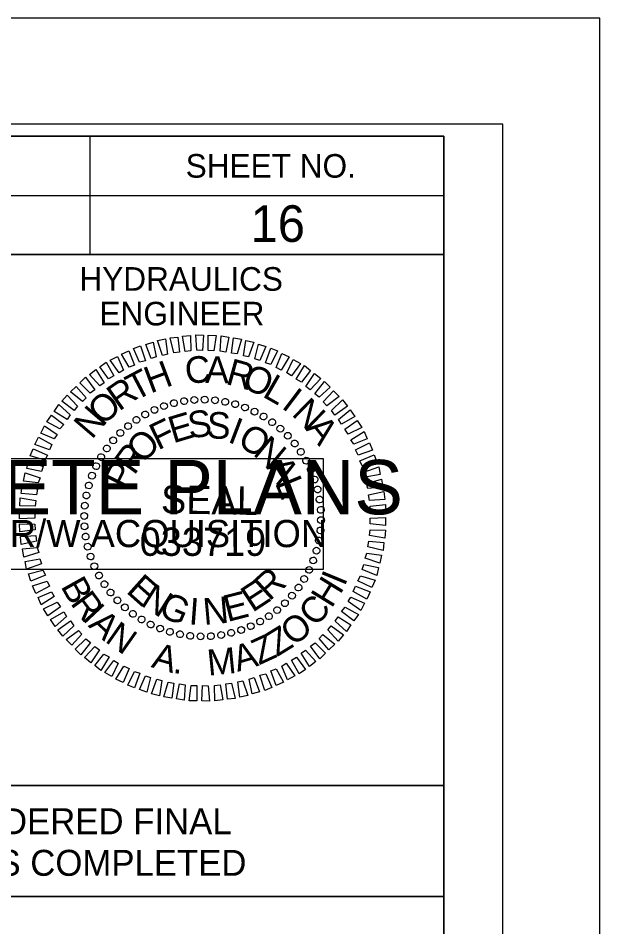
# Model space of a CAD drawing. Extents: x 1779926 to 1781626, y 618464 to 619564.
# Drawn here: x 1781502.8 to 1781626, y 619371.7 to 619564.2 of the extents above; entities that cross this region are included whole.
import ezdxf

# ---------------------------------------------------------------- set-up
doc = ezdxf.new("R2010")
doc.units = 0
for name, color, linetype in [('Old_Level_58', 7, 'Continuous'), ('Sheet Data Field CELL', 7, 'Continuous'), ('Sheet Plot Border Inside CELL', 7, 'Continuous'), ('Sheet Plot Border Outside CELL', 7, 'Continuous'), ('Sheet Professional Seal CELL', 7, 'Continuous'), ('Sheet Profile CELL', 7, 'Continuous'), ('Sheet Profile Grid Major CELL', 7, 'Continuous'), ('Sheet Profile Grid Minor CELL', 7, 'Continuous'), ('Sheet Sticker Exception Certification CELL', 7, 'Continuous'), ('Sheet Sticker Incomplete CELL', 7, 'Continuous')]:
    doc.layers.add(name, color=color, linetype=linetype)

msp = doc.modelspace()

# ---------------------------------------------------------------- linework, layer by layer
at = {"layer": 'Old_Level_58'}
msp.add_lwpolyline([(1781392.9, 619378.14), (1781592.95, 619378.14), (1781592.95, 619314.19), (1781392.9, 619314.19)], close=True, dxfattribs=at)
at = {"layer": 'Sheet Plot Border Inside CELL'}
msp.add_lwpolyline([(1779938.96, 618486.64), (1781605.46, 618486.64), (1781605.46, 619541.74), (1779938.96, 619541.74)], close=True, dxfattribs=at)
at = {"layer": 'Sheet Plot Border Outside CELL'}
msp.add_lwpolyline([(1779925.96, 618464.19), (1781625.96, 618464.19), (1781625.96, 619564.19), (1779925.96, 619564.19)], close=True, dxfattribs=at)
at = {"layer": 'Sheet Professional Seal CELL'}
for p, q in [((1781535.76, 619482.64), (1781535.76, 619482.64)), ((1781537.96, 619483.04), (1781537.96, 619483.04)), ((1781540.11, 619483.34), (1781540.11, 619483.34)), ((1781542.31, 619483.39), (1781542.31, 619483.39)), ((1781544.51, 619483.24), (1781544.51, 619483.24)), ((1781546.66, 619482.89), (1781546.66, 619482.89)), ((1781548.76, 619482.44), (1781548.76, 619482.44)), ((1781531.66, 619481.24), (1781531.66, 619481.24)), ((1781533.66, 619482.04), (1781533.66, 619482.04)), ((1781550.86, 619481.74), (1781550.86, 619481.74)), ((1781552.86, 619480.84), (1781552.86, 619480.84)), ((1781527.81, 619479.09), (1781527.81, 619479.09)), ((1781529.71, 619480.24), (1781529.71, 619480.24)), ((1781554.81, 619479.84), (1781554.81, 619479.84)), ((1781556.61, 619478.59), (1781556.61, 619478.59)), ((1781526.06, 619477.84), (1781526.06, 619477.84)), ((1781558.36, 619477.24), (1781558.36, 619477.24)), ((1781522.91, 619474.79), (1781522.91, 619474.79)), ((1781524.41, 619476.34), (1781524.41, 619476.34)), ((1781559.91, 619475.74), (1781559.91, 619475.74)), ((1781521.56, 619473.04), (1781521.56, 619473.04)), ((1781561.41, 619474.09), (1781561.41, 619474.09)), ((1781520.31, 619471.24), (1781520.31, 619471.24)), ((1781562.66, 619472.34), (1781562.66, 619472.34)), ((1781519.31, 619469.29), (1781519.31, 619469.29)), ((1781563.81, 619470.44), (1781563.81, 619470.44)), ((1781518.41, 619467.29), (1781518.41, 619467.29)), ((1781564.81, 619468.49), (1781564.81, 619468.49)), ((1781517.71, 619465.19), (1781517.71, 619465.19)), ((1781565.61, 619466.49), (1781565.61, 619466.49)), ((1781517.26, 619463.09), (1781517.26, 619463.09)), ((1781566.21, 619464.39), (1781566.21, 619464.39)), ((1781566.61, 619462.19), (1781566.61, 619462.19)), ((1781516.91, 619460.94), (1781516.91, 619460.94)), ((1781566.91, 619460.04), (1781566.91, 619460.04)), ((1781516.76, 619458.74), (1781516.76, 619458.74)), ((1781541.86, 619458.29), (1781541.86, 619458.29)), ((1781566.96, 619457.84), (1781566.96, 619457.84)), ((1781516.81, 619456.54), (1781516.81, 619456.54)), ((1781566.81, 619455.64), (1781566.81, 619455.64)), ((1781517.11, 619454.39), (1781517.11, 619454.39)), ((1781566.46, 619453.49), (1781566.46, 619453.49)), ((1781517.51, 619452.19), (1781517.51, 619452.19)), ((1781518.11, 619450.09), (1781518.11, 619450.09)), ((1781566.01, 619451.39), (1781566.01, 619451.39)), ((1781518.91, 619448.09), (1781518.91, 619448.09)), ((1781565.31, 619449.29), (1781565.31, 619449.29)), ((1781519.91, 619446.14), (1781519.91, 619446.14)), ((1781564.41, 619447.29), (1781564.41, 619447.29)), ((1781521.06, 619444.24), (1781521.06, 619444.24)), ((1781563.41, 619445.34), (1781563.41, 619445.34)), ((1781522.31, 619442.49), (1781522.31, 619442.49)), ((1781562.16, 619443.54), (1781562.16, 619443.54)), ((1781523.81, 619440.84), (1781523.81, 619440.84)), ((1781559.31, 619440.24), (1781559.31, 619440.24)), ((1781560.81, 619441.79), (1781560.81, 619441.79)), ((1781525.36, 619439.34), (1781525.36, 619439.34)), ((1781557.66, 619438.74), (1781557.66, 619438.74)), ((1781527.11, 619437.99), (1781527.11, 619437.99)), ((1781528.91, 619436.74), (1781528.91, 619436.74)), ((1781554.01, 619436.34), (1781554.01, 619436.34)), ((1781555.91, 619437.49), (1781555.91, 619437.49)), ((1781530.86, 619435.74), (1781530.86, 619435.74)), ((1781532.86, 619434.84), (1781532.86, 619434.84)), ((1781550.06, 619434.54), (1781550.06, 619434.54)), ((1781552.06, 619435.34), (1781552.06, 619435.34)), ((1781534.96, 619434.14), (1781534.96, 619434.14)), ((1781537.06, 619433.69), (1781537.06, 619433.69)), ((1781539.21, 619433.34), (1781539.21, 619433.34)), ((1781541.41, 619433.19), (1781541.41, 619433.19)), ((1781543.61, 619433.24), (1781543.61, 619433.24)), ((1781545.76, 619433.54), (1781545.76, 619433.54)), ((1781547.96, 619433.94), (1781547.96, 619433.94))]:
    msp.add_line(p, q, dxfattribs=at)
for points in [[(1781533.36, 619492.74), (1781532.31, 619495.89), (1781534.01, 619496.24), (1781534.41, 619492.99)], [(1781535.76, 619493.29), (1781534.96, 619496.49), (1781536.61, 619496.64), (1781536.96, 619493.44)], [(1781538.16, 619493.59), (1781537.61, 619496.79), (1781539.31, 619496.99), (1781539.36, 619493.74)], [(1781540.66, 619493.84), (1781540.41, 619497.09), (1781542.06, 619497.04), (1781541.86, 619493.79)], [(1781543.06, 619493.79), (1781543.06, 619497.04), (1781544.71, 619496.99), (1781544.26, 619493.74)], [(1781545.56, 619493.64), (1781545.76, 619496.89), (1781547.41, 619496.59), (1781546.76, 619493.44)], [(1781547.96, 619493.24), (1781548.41, 619496.44), (1781550.06, 619496.19), (1781549.16, 619493.09)], [(1781550.51, 619492.69), (1781551.01, 619495.94), (1781552.71, 619495.54), (1781551.56, 619492.44)], [(1781528.51, 619491.29), (1781527.21, 619494.19), (1781528.71, 619494.79), (1781529.76, 619491.59)], [(1781530.96, 619492.09), (1781529.81, 619495.09), (1781531.36, 619495.54), (1781532.01, 619492.44)], [(1781552.91, 619492.04), (1781553.66, 619495.14), (1781555.21, 619494.64), (1781553.96, 619491.69)], [(1781555.16, 619491.14), (1781556.31, 619494.29), (1781557.71, 619493.69), (1781556.31, 619490.79)], [(1781524.16, 619489.04), (1781522.31, 619491.74), (1781523.86, 619492.54), (1781525.11, 619489.64)], [(1781526.31, 619490.24), (1781524.71, 619493.04), (1781526.26, 619493.74), (1781527.41, 619490.69)], [(1781557.41, 619490.19), (1781558.66, 619493.14), (1781560.21, 619492.44), (1781558.51, 619489.64)], [(1781521.96, 619487.79), (1781520.11, 619490.34), (1781521.41, 619491.29), (1781523.06, 619488.39)], [(1781559.71, 619489.04), (1781561.06, 619491.89), (1781562.56, 619491.04), (1781560.66, 619488.44)], [(1781561.66, 619487.69), (1781563.41, 619490.59), (1781564.71, 619489.54), (1781562.76, 619487.09)], [(1781518.06, 619484.74), (1781515.86, 619486.94), (1781517.06, 619488.14), (1781519.01, 619485.44)], [(1781520.06, 619486.29), (1781517.91, 619488.69), (1781519.26, 619489.74), (1781521.01, 619486.94)], [(1781563.71, 619486.19), (1781565.56, 619488.94), (1781566.86, 619487.84), (1781564.66, 619485.49)], [(1781516.41, 619482.99), (1781513.86, 619485.04), (1781515.11, 619486.19), (1781517.21, 619483.79)], [(1781565.61, 619484.64), (1781567.66, 619487.24), (1781568.86, 619486.04), (1781566.56, 619483.89)], [(1781514.66, 619481.09), (1781512.06, 619483.04), (1781513.16, 619484.34), (1781515.36, 619481.99)], [(1781567.41, 619482.89), (1781569.56, 619485.24), (1781570.76, 619484.04), (1781568.16, 619482.09)], [(1781513.16, 619479.19), (1781510.46, 619480.89), (1781511.41, 619482.34), (1781513.81, 619480.14)], [(1781569.16, 619481.09), (1781571.46, 619483.34), (1781572.51, 619481.99), (1781569.86, 619480.09)], [(1781570.66, 619479.14), (1781573.11, 619481.24), (1781574.06, 619479.79), (1781571.26, 619478.19)], [(1781511.66, 619477.19), (1781508.86, 619478.69), (1781509.86, 619480.09), (1781512.46, 619478.09)], [(1781571.96, 619477.09), (1781574.61, 619478.99), (1781575.56, 619477.49), (1781572.66, 619476.09)], [(1781510.46, 619475.04), (1781507.61, 619476.29), (1781508.36, 619477.84), (1781511.06, 619475.99)], [(1781573.26, 619474.89), (1781576.06, 619476.64), (1781576.71, 619475.09), (1781573.86, 619473.94)], [(1781509.46, 619472.74), (1781506.36, 619473.89), (1781507.11, 619475.44), (1781509.96, 619473.84)], [(1781508.46, 619470.54), (1781505.36, 619471.44), (1781506.01, 619472.99), (1781509.01, 619471.59)], [(1781574.26, 619472.74), (1781577.21, 619474.24), (1781577.86, 619472.64), (1781574.76, 619471.64)], [(1781575.16, 619470.39), (1781578.21, 619471.69), (1781578.76, 619470.14), (1781575.66, 619469.34)], [(1781507.71, 619468.14), (1781504.61, 619468.79), (1781504.96, 619470.44), (1781508.11, 619469.19)], [(1781575.96, 619467.99), (1781579.16, 619469.14), (1781579.46, 619467.49), (1781576.31, 619466.94)], [(1781507.06, 619465.74), (1781503.96, 619466.14), (1781504.31, 619467.84), (1781507.46, 619466.79)], [(1781506.66, 619463.19), (1781503.46, 619463.49), (1781503.66, 619465.19), (1781506.91, 619464.39)], [(1781576.56, 619465.59), (1781579.71, 619466.54), (1781580.01, 619464.84), (1781576.86, 619464.54)], [(1781577.01, 619463.19), (1781580.26, 619463.89), (1781580.41, 619462.19), (1781577.21, 619461.99)], [(1781506.41, 619460.79), (1781503.16, 619460.89), (1781503.26, 619462.54), (1781506.51, 619461.99)], [(1781577.31, 619460.79), (1781580.56, 619461.19), (1781580.66, 619459.49), (1781577.41, 619459.59)], [(1781506.36, 619458.29), (1781503.11, 619458.14), (1781503.11, 619459.84), (1781506.36, 619459.49)], [(1781577.36, 619458.29), (1781580.61, 619458.44), (1781580.61, 619456.74), (1781577.36, 619457.09)], [(1781506.41, 619455.79), (1781503.16, 619455.39), (1781503.06, 619457.09), (1781506.31, 619456.99)], [(1781577.31, 619455.79), (1781580.56, 619455.69), (1781580.46, 619454.04), (1781577.21, 619454.59)], [(1781506.71, 619453.39), (1781503.46, 619452.69), (1781503.31, 619454.39), (1781506.51, 619454.59)], [(1781507.16, 619450.99), (1781504.01, 619450.04), (1781503.71, 619451.74), (1781506.86, 619452.04)], [(1781577.06, 619453.39), (1781580.26, 619453.09), (1781580.06, 619451.39), (1781576.81, 619452.19)], [(1781507.76, 619448.59), (1781504.56, 619447.44), (1781504.26, 619449.09), (1781507.41, 619449.64)], [(1781576.66, 619450.84), (1781579.76, 619450.44), (1781579.41, 619448.74), (1781576.26, 619449.79)], [(1781576.01, 619448.44), (1781579.11, 619447.79), (1781578.76, 619446.14), (1781575.61, 619447.39)], [(1781508.56, 619446.19), (1781505.51, 619444.89), (1781504.96, 619446.44), (1781508.06, 619447.24)], [(1781575.26, 619446.04), (1781578.36, 619445.14), (1781577.71, 619443.59), (1781574.71, 619444.99)], [(1781509.46, 619443.84), (1781506.51, 619442.34), (1781505.86, 619443.94), (1781508.96, 619444.94)], [(1781574.26, 619443.84), (1781577.36, 619442.69), (1781576.61, 619441.14), (1781573.76, 619442.74)], [(1781510.46, 619441.69), (1781507.66, 619439.94), (1781507.01, 619441.49), (1781509.86, 619442.64)], [(1781511.76, 619439.49), (1781509.11, 619437.59), (1781508.16, 619439.09), (1781511.06, 619440.49)], [(1781573.26, 619441.54), (1781576.11, 619440.29), (1781575.36, 619438.74), (1781572.66, 619440.59)], [(1781513.06, 619437.44), (1781510.61, 619435.34), (1781509.66, 619436.79), (1781512.46, 619438.39)], [(1781572.06, 619439.39), (1781574.86, 619437.89), (1781573.86, 619436.49), (1781571.26, 619438.49)], [(1781514.56, 619435.49), (1781512.26, 619433.24), (1781511.21, 619434.59), (1781513.86, 619436.49)], [(1781570.56, 619437.39), (1781573.26, 619435.69), (1781572.31, 619434.24), (1781569.91, 619436.44)], [(1781516.31, 619433.69), (1781514.16, 619431.34), (1781512.96, 619432.54), (1781515.56, 619434.49)], [(1781569.06, 619435.49), (1781571.66, 619433.54), (1781570.56, 619432.24), (1781568.36, 619434.59)], [(1781518.11, 619431.94), (1781516.06, 619429.34), (1781514.86, 619430.54), (1781517.16, 619432.69)], [(1781567.31, 619433.59), (1781569.86, 619431.54), (1781568.61, 619430.39), (1781566.51, 619432.79)], [(1781520.01, 619430.39), (1781518.16, 619427.64), (1781516.86, 619428.74), (1781519.06, 619431.09)], [(1781565.66, 619431.84), (1781567.86, 619429.64), (1781566.66, 619428.44), (1781564.71, 619431.14)], [(1781522.06, 619428.89), (1781520.31, 619425.99), (1781519.01, 619427.04), (1781520.96, 619429.49)], [(1781561.76, 619428.79), (1781563.61, 619426.24), (1781562.31, 619425.29), (1781560.66, 619428.19)], [(1781563.66, 619430.29), (1781565.81, 619427.89), (1781564.46, 619426.84), (1781562.71, 619429.64)], [(1781524.01, 619427.54), (1781522.66, 619424.69), (1781521.16, 619425.54), (1781523.06, 619428.14)], [(1781526.31, 619426.39), (1781525.06, 619423.44), (1781523.51, 619424.14), (1781525.21, 619426.94)], [(1781559.56, 619427.54), (1781561.41, 619424.84), (1781559.86, 619424.04), (1781558.61, 619426.94)], [(1781528.56, 619425.44), (1781527.41, 619422.29), (1781526.01, 619422.89), (1781527.41, 619425.79)], [(1781530.81, 619424.54), (1781530.06, 619421.44), (1781528.51, 619421.94), (1781529.76, 619424.89)], [(1781555.21, 619425.29), (1781556.51, 619422.39), (1781555.01, 619421.79), (1781553.96, 619424.99)], [(1781557.41, 619426.34), (1781559.01, 619423.54), (1781557.46, 619422.84), (1781556.31, 619425.89)], [(1781533.21, 619423.89), (1781532.71, 619420.64), (1781531.01, 619421.04), (1781532.16, 619424.14)], [(1781535.76, 619423.34), (1781535.31, 619420.14), (1781533.66, 619420.39), (1781534.56, 619423.49)], [(1781538.16, 619422.94), (1781537.96, 619419.69), (1781536.31, 619419.99), (1781536.96, 619423.14)], [(1781540.66, 619422.79), (1781540.66, 619419.54), (1781539.01, 619419.59), (1781539.46, 619422.84)], [(1781543.06, 619422.74), (1781543.31, 619419.49), (1781541.66, 619419.54), (1781541.86, 619422.79)], [(1781545.56, 619422.99), (1781546.11, 619419.79), (1781544.41, 619419.59), (1781544.36, 619422.84)], [(1781547.96, 619423.29), (1781548.76, 619420.09), (1781547.11, 619419.94), (1781546.76, 619423.14)], [(1781550.36, 619423.84), (1781551.41, 619420.69), (1781549.71, 619420.34), (1781549.31, 619423.59)], [(1781552.76, 619424.49), (1781553.91, 619421.49), (1781552.36, 619421.04), (1781551.71, 619424.14)]]:
    msp.add_lwpolyline(points, close=True, dxfattribs=at)
for centre, major_axis in [((1781533.69, 619482.01), (-0.234, 0.681)), ((1781535.79, 619482.63), (-0.174, 0.699)), ((1781537.93, 619483.06), (-0.113, 0.711)), ((1781540.11, 619483.31), (-0.05, 0.718)), ((1781542.29, 619483.37), (0.013, 0.72)), ((1781544.48, 619483.24), (0.075, 0.716)), ((1781546.64, 619482.91), (0.137, 0.707)), ((1781548.77, 619482.4), (0.198, 0.692)), ((1781550.84, 619481.71), (0.258, 0.672)), ((1781529.7, 619480.23), (-0.349, 0.63)), ((1781531.66, 619481.2), (-0.293, 0.658)), ((1781552.85, 619480.83), (0.316, 0.647)), ((1781554.77, 619479.79), (0.371, 0.617)), ((1781526.07, 619477.78), (-0.453, 0.56)), ((1781527.83, 619479.09), (-0.403, 0.597)), ((1781556.6, 619478.58), (0.423, 0.582)), ((1781524.43, 619476.33), (-0.5, 0.518)), ((1781558.31, 619477.22), (0.472, 0.543)), ((1781522.93, 619474.75), (-0.543, 0.472)), ((1781559.9, 619475.72), (0.518, 0.5)), ((1781561.35, 619474.08), (0.56, 0.453)), ((1781521.57, 619473.03), (-0.582, 0.423)), ((1781562.65, 619472.32), (0.597, 0.403)), ((1781520.36, 619471.21), (-0.617, 0.371)), ((1781563.79, 619470.45), (0.63, 0.349)), ((1781519.31, 619469.29), (-0.647, 0.316)), ((1781564.77, 619468.49), (0.658, 0.293)), ((1781518.44, 619467.28), (-0.672, 0.258)), ((1781565.57, 619466.46), (0.681, 0.234)), ((1781517.75, 619465.21), (-0.692, 0.198)), ((1781566.19, 619464.36), (0.699, 0.174)), ((1781517.24, 619463.08), (-0.707, 0.137)), ((1781516.91, 619460.91), (-0.716, 0.075)), ((1781566.63, 619462.22), (0.711, 0.113)), ((1781516.78, 619458.73), (-0.72, 0.013)), ((1781566.88, 619460.04), (0.718, 0.05)), ((1781566.93, 619457.86), (0.72, -0.013)), ((1781516.84, 619456.54), (-0.718, -0.05)), ((1781566.8, 619455.67), (0.716, -0.075)), ((1781517.09, 619454.37), (-0.711, -0.113)), ((1781566.48, 619453.51), (0.707, -0.137)), ((1781517.52, 619452.23), (-0.699, -0.174)), ((1781565.96, 619451.38), (0.692, -0.198)), ((1781518.14, 619450.13), (-0.681, -0.234)), ((1781565.27, 619449.31), (0.672, -0.258)), ((1781518.94, 619448.09), (-0.658, -0.293)), ((1781564.4, 619447.3), (0.647, -0.316)), ((1781519.92, 619446.13), (-0.63, -0.349)), ((1781563.35, 619445.38), (0.617, -0.371)), ((1781521.06, 619444.27), (-0.597, -0.403)), ((1781562.15, 619443.55), (0.582, -0.423)), ((1781522.37, 619442.51), (-0.56, -0.453)), ((1781560.78, 619441.84), (0.543, -0.472)), ((1781523.82, 619440.87), (-0.518, -0.5)), ((1781525.4, 619439.37), (-0.472, -0.543)), ((1781559.28, 619440.25), (0.5, -0.518)), ((1781527.11, 619438), (-0.423, -0.582)), ((1781555.88, 619437.5), (0.403, -0.597)), ((1781557.64, 619438.8), (0.453, -0.56)), ((1781528.94, 619436.8), (-0.371, -0.617)), ((1781530.86, 619435.75), (-0.316, -0.647)), ((1781552.06, 619435.38), (0.293, -0.658)), ((1781554.02, 619436.36), (0.349, -0.63)), ((1781532.87, 619434.88), (-0.258, -0.672)), ((1781534.94, 619434.18), (-0.198, -0.692)), ((1781537.07, 619433.67), (-0.137, -0.707)), ((1781545.78, 619433.52), (0.113, -0.711)), ((1781547.92, 619433.96), (0.174, -0.699)), ((1781550.02, 619434.58), (0.234, -0.681)), ((1781539.23, 619433.35), (-0.075, -0.716)), ((1781541.42, 619433.22), (-0.013, -0.72)), ((1781543.61, 619433.27), (0.05, -0.718))]:
    msp.add_ellipse(centre, major_axis=major_axis, ratio=0.999708, dxfattribs=at)
at = {"layer": 'Sheet Profile CELL'}
for p, q in [((1781517.96, 619539.14), (1781517.96, 619514.14)), ((1781392.91, 619526.64), (1781592.96, 619526.64))]:
    msp.add_line(p, q, dxfattribs=at)
for points in [[(1781592.96, 619539.19), (1780092.96, 619539.19), (1780092.96, 618489.19), (1781592.96, 618489.19)], [(1781392.91, 619539.19), (1781592.96, 619539.19), (1781592.96, 619514.14), (1781392.91, 619514.14)], [(1781492.96, 619514.14), (1781592.96, 619514.14), (1781592.96, 619401.64), (1781492.96, 619401.64)]]:
    msp.add_lwpolyline(points, close=True, dxfattribs=at)
at = {"layer": 'Sheet Profile Grid Major CELL'}
msp.add_lwpolyline([(1781542.96, 619314.19), (1781542.96, 619039.19), (1781592.96, 619039.19), (1781592.96, 619389.19)], dxfattribs=at)
at = {"layer": 'Sheet Sticker Exception Certification CELL'}
for p, q in [((1781392.91, 619401.64), (1781592.95, 619401.64)), ((1781392.91, 619401.64), (1781592.95, 619401.64)), ((1781592.95, 619401.63), (1781592.95, 619378.13)), ((1781592.95, 619401.63), (1781592.95, 619378.13)), ((1781592.95, 619378.14), (1781392.91, 619378.14)), ((1781592.95, 619378.14), (1781392.91, 619378.14))]:
    msp.add_line(p, q, dxfattribs=at)
at = {"layer": 'Sheet Sticker Incomplete CELL'}
msp.add_lwpolyline([(1781420.37, 619447.38), (1781420.37, 619470.88), (1781567.37, 619470.88), (1781567.37, 619447.38)], close=True, dxfattribs=at)

# ---------------------------------------------------------------- texts
at = {"layer": 'Sheet Data Field CELL'}
msp.add_text('16', height=7.75, dxfattribs=at).set_placement((1781552, 619516.8))
at = {"layer": 'Sheet Professional Seal CELL'}
for s, height, rotation, p in [('C', 5.64, 6.2199, (1781538.41, 619486.64)), ('A', 5.64, 359.0203, (1781542.36, 619486.94)), ('R', 5.64, 344.6211, (1781546.56, 619486.74)), ('T', 5.64, 27.8198, (1781527.56, 619482.99)), ('H', 5.64, 20.6195, (1781530.81, 619484.64)), ('O', 5.64, 337.4212, (1781549.91, 619485.99)), ('L', 5.64, 330.2209, (1781554.31, 619484.14)), ('R', 5.64, 35.0205, (1781524.16, 619480.79)), ('O', 5.64, 42.2217, (1781520.71, 619477.69)), ('I', 5.64, 323.0201, (1781558.36, 619481.74)), ('N', 5.64, 315.8189, (1781560.51, 619480.19)), ('N', 5.64, 49.4235, (1781518.41, 619474.79)), ('E', 5.64, 16.6111, (1781535.61, 619474.09)), ('S', 5.64, 7.2556, (1781539.06, 619475.14)), ('S', 5.64, 357.9004, (1781542.66, 619475.19)), ('F', 5.64, 25.967, (1781532.41, 619472.59)), ('I', 5.64, 339.1896, (1781546.96, 619474.49)), ('A', 5.64, 308.6172, (1781563.46, 619477.24)), ('O', 5.64, 44.6812, (1781529.11, 619469.64)), ('O', 5.64, 329.8335, (1781548.96, 619473.79)), ('N', 5.64, 320.4766, (1781552.31, 619471.79)), ('R', 5.64, 54.0397, (1781527.36, 619467.19)), ('P', 5.64, 63.3989, (1781525.76, 619463.99)), ('A', 5.64, 301.7603, (1781555.16, 619469.19)), ('L', 5.64, 292.4008, (1781557.11, 619465.74)), ('SEAL', 5.998, 359, (1781533.01, 619459.29)), ('E', 5.64, 318.2769, (1781525.46, 619442.64)), ('R', 5.64, 42.4814, (1781555.96, 619440.54)), ('N', 5.64, 327.634, (1781528.46, 619439.94)), ('E', 5.64, 33.1241, (1781552.41, 619438.19)), ('G', 5.64, 336.9902, (1781532.26, 619437.69)), ('E', 5.64, 14.4118, (1781547.11, 619436.24)), ('I', 5.64, 355.7012, (1781538.81, 619435.79)), ('N', 5.64, 5.0564, (1781542.16, 619435.64))]:
    msp.add_text(s, height=height, rotation=rotation, dxfattribs=at).set_placement(p)
at = {"layer": 'Sheet Profile CELL'}
for s, p in [('SHEET NO.', (1781538.27, 619530.4)), ('HYDRAULICS', (1781515.77, 619506.45)), ('ENGINEER', (1781520.02, 619499.1))]:
    msp.add_text(s, height=5, dxfattribs=at).set_placement(p)
at = {"layer": 'Sheet Profile Grid Minor CELL'}
msp.add_text('033719', height=5.998, dxfattribs=at).set_placement((1781528.54, 619450.28))
for s, rotation, p in [('B', 299.1529, (1781511.71, 619443.85)), ('H', 58.3478, (1781569.17, 619439.02)), ('I', 67.5926, (1781571.91, 619443.66)), ('R', 306.2797, (1781513.73, 619440.22)), ('I', 313.2061, (1781516.12, 619436.96)), ('C', 49.4751, (1781565.87, 619435.04)), ('A', 316.7266, (1781517.48, 619435.42)), ('N', 324.9124, (1781520.98, 619432.19)), ('O', 38.7706, (1781561.13, 619430.98)), ('Z', 31.6438, (1781557.59, 619428.8)), ('Z', 24.517, (1781553.81, 619427.08)), ('A', 344.2893, (1781530.82, 619426.74)), ('M', 5.6554, (1781543.08, 619424.89)), ('A', 16.3312, (1781549.25, 619425.69)), ('.', 352.4751, (1781535.43, 619425.49))]:
    msp.add_text(s, height=5.5, rotation=rotation, dxfattribs=at).set_placement(p)
at = {"layer": 'Sheet Sticker Exception Certification CELL'}
for s, p in [('DOCUMENT NOT CONSIDERED FINAL', (1781413.98, 619391.3)), ('DOCUMENT NOT CONSIDERED FINAL', (1781413.98, 619391.3)), ('UNLESS ALL SIGNATURES COMPLETED', (1781408.91, 619382.5)), ('UNLESS ALL SIGNATURES COMPLETED', (1781408.91, 619382.5))]:
    msp.add_text(s, height=5.5, dxfattribs=at).set_placement(p)
at = {"layer": 'Sheet Sticker Incomplete CELL'}
for s, height, p in [('INCOMPLETE PLANS', 11.52, (1781429.32, 619459.08)), ('DO NOT USE FOR R/W ACQUISITION', 5.76, (1781432.57, 619452.13))]:
    msp.add_text(s, height=height, dxfattribs=at).set_placement(p)

doc.saveas('drawing.dxf')
